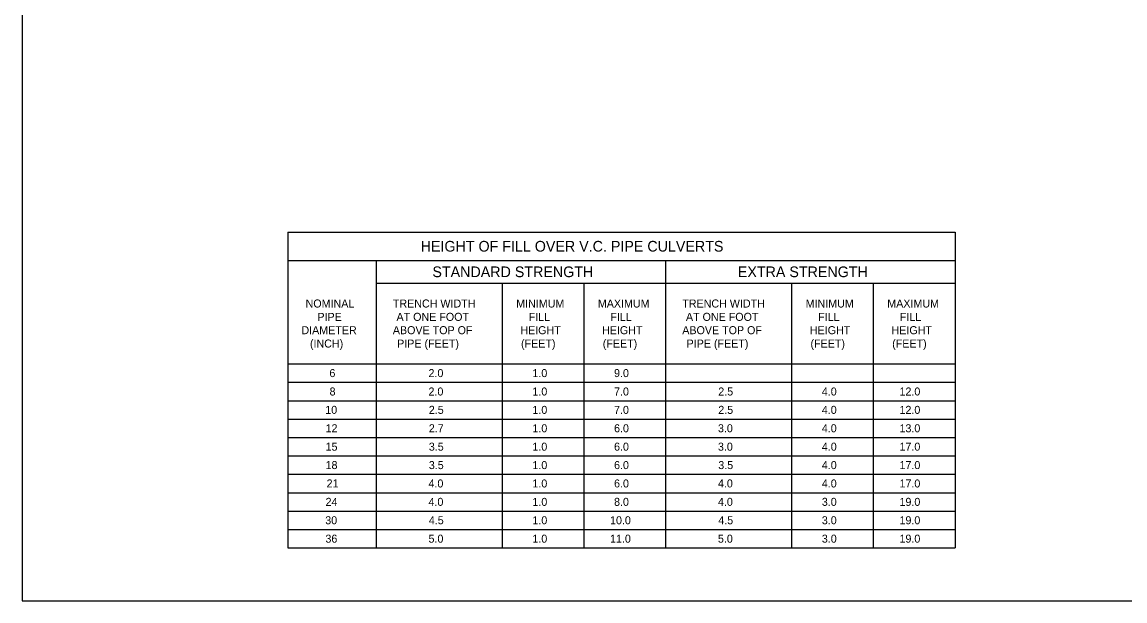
# Model space of a CAD drawing. Extents: x -439.1 to -407.9, y -458.1 to -436.2.
# Drawn here: x -439.11 to -418.43, y -458.05 to -447.2 of the extents above; entities that cross this region are included whole.
import ezdxf

# ---------------------------------------------------------------- set-up
doc = ezdxf.new("R2010")
doc.units = 0
for name, color, linetype in [('Bridge-Named Boundary', 7, 'Continuous'), ('Level 4', 7, 'Continuous'), ('Level 45', 7, 'Continuous')]:
    doc.layers.add(name, color=color, linetype=linetype)

msp = doc.modelspace()

# ---------------------------------------------------------------- linework, layer by layer
at = {"layer": 'Bridge-Named Boundary'}
msp.add_lwpolyline([(-439.109, -458.051), (-407.859, -458.051), (-407.859, -437.676), (-439.109, -437.676)], close=True, dxfattribs=at)
at = {"layer": 'Level 4'}
for p, q in [((-434.128, -451.139), (-434.128, -457.056)), ((-434.128, -451.139), (-421.616, -451.139)), ((-421.616, -451.139), (-421.616, -457.056)), ((-434.128, -451.67), (-421.616, -451.67)), ((-432.47, -451.67), (-432.47, -457.056)), ((-427.043, -451.67), (-427.043, -457.056)), ((-432.47, -452.095), (-421.616, -452.095)), ((-430.106, -452.095), (-430.106, -457.056)), ((-428.575, -452.095), (-428.575, -457.056)), ((-424.679, -452.095), (-424.679, -457.056)), ((-423.148, -452.095), (-423.148, -457.056)), ((-434.128, -453.609), (-421.616, -453.609)), ((-434.128, -453.953), (-421.616, -453.953)), ((-434.128, -454.298), (-421.616, -454.298)), ((-434.128, -454.643), (-421.616, -454.643)), ((-434.128, -454.987), (-421.616, -454.987)), ((-434.128, -455.332), (-421.616, -455.332)), ((-434.128, -455.677), (-421.616, -455.677)), ((-434.128, -456.022), (-421.616, -456.022)), ((-434.128, -456.366), (-421.616, -456.366)), ((-434.128, -456.711), (-421.616, -456.711)), ((-434.128, -457.056), (-421.616, -457.056))]:
    msp.add_line(p, q, dxfattribs=at)

# ---------------------------------------------------------------- texts
for s, p in [('HEIGHT OF FILL OVER V.C. PIPE CULVERTS', (-431.635, -451.504)), ('STANDARD STRENGTH', (-431.415, -451.983)), ('EXTRA STRENGTH', (-425.688, -451.983))]:
    msp.add_text(s, height=0.2, dxfattribs=at).set_placement(p)
at = {"layer": 'Level 45'}
for s, p in [('NOMINAL', (-433.793, -452.552)), ('TRENCH WIDTH', (-432.157, -452.552)), ('MINIMUM', (-429.844, -452.552)), ('MAXIMUM', (-428.313, -452.552)), ('TRENCH WIDTH', (-426.73, -452.552)), ('MINIMUM', (-424.417, -452.552)), ('MAXIMUM', (-422.886, -452.552)), ('PIPE', (-433.571, -452.802)), ('AT ONE FOOT', (-432.088, -452.802)), ('FILL', (-429.609, -452.802)), ('FILL', (-428.078, -452.802)), ('AT ONE FOOT', (-426.661, -452.802)), ('FILL', (-424.182, -452.802)), ('FILL', (-422.651, -452.802)), ('DIAMETER', (-433.871, -453.052)), ('ABOVE TOP OF', (-432.157, -453.052)), ('HEIGHT', (-429.766, -453.052)), ('HEIGHT', (-428.234, -453.052)), ('ABOVE TOP OF', (-426.73, -453.052)), ('HEIGHT', (-424.338, -453.052)), ('HEIGHT', (-422.807, -453.052)), ('(INCH)', (-433.711, -453.302)), ('PIPE (FEET)', (-432.076, -453.302)), ('(FEET)', (-429.753, -453.302)), ('(FEET)', (-428.221, -453.302)), ('PIPE (FEET)', (-426.649, -453.302)), ('(FEET)', (-424.326, -453.302)), ('(FEET)', (-422.794, -453.302)), ('6', (-433.346, -453.856)), ('2.0', (-431.488, -453.856)), ('1.0', (-429.54, -453.856)), ('9.0', (-428.009, -453.856)), ('8', (-433.343, -454.201)), ('2.0', (-431.488, -454.201)), ('1.0', (-429.54, -454.201)), ('7.0', (-428.009, -454.201)), ('2.5', (-426.055, -454.201)), ('4.0', (-424.113, -454.201)), ('12.0', (-422.657, -454.201)), ('10', (-433.424, -454.545)), ('2.5', (-431.482, -454.545)), ('1.0', (-429.54, -454.545)), ('7.0', (-428.009, -454.545)), ('2.5', (-426.055, -454.545)), ('4.0', (-424.113, -454.545)), ('12.0', (-422.657, -454.545)), ('12', (-433.418, -454.89)), ('2.7', (-431.482, -454.89)), ('1.0', (-429.54, -454.89)), ('6.0', (-428.009, -454.89)), ('3.0', (-426.061, -454.89)), ('4.0', (-424.113, -454.89)), ('13.0', (-422.657, -454.89)), ('15', (-433.418, -455.235)), ('3.5', (-431.482, -455.235)), ('1.0', (-429.54, -455.235)), ('6.0', (-428.009, -455.235)), ('3.0', (-426.061, -455.235)), ('4.0', (-424.113, -455.235)), ('17.0', (-422.657, -455.235)), ('18', (-433.418, -455.58)), ('3.5', (-431.482, -455.58)), ('1.0', (-429.54, -455.58)), ('6.0', (-428.009, -455.58)), ('3.5', (-426.055, -455.58)), ('4.0', (-424.113, -455.58)), ('17.0', (-422.657, -455.58)), ('21', (-433.399, -455.924)), ('4.0', (-431.488, -455.924)), ('1.0', (-429.54, -455.924)), ('6.0', (-428.009, -455.924)), ('4.0', (-426.061, -455.924)), ('4.0', (-424.113, -455.924)), ('17.0', (-422.657, -455.924)), ('24', (-433.418, -456.269)), ('4.0', (-431.488, -456.269)), ('1.0', (-429.54, -456.269)), ('8.0', (-428.009, -456.269)), ('4.0', (-426.061, -456.269)), ('3.0', (-424.113, -456.269)), ('19.0', (-422.657, -456.269)), ('30', (-433.424, -456.614)), ('4.5', (-431.482, -456.614)), ('1.0', (-429.54, -456.614)), ('10.0', (-428.084, -456.614)), ('4.5', (-426.055, -456.614)), ('3.0', (-424.113, -456.614)), ('19.0', (-422.657, -456.614)), ('36', (-433.421, -456.959)), ('5.0', (-431.488, -456.959)), ('1.0', (-429.54, -456.959)), ('11.0', (-428.084, -456.959)), ('5.0', (-426.061, -456.959)), ('3.0', (-424.113, -456.959)), ('19.0', (-422.657, -456.959))]:
    msp.add_text(s, height=0.15, dxfattribs=at).set_placement(p)

doc.saveas('drawing.dxf')
